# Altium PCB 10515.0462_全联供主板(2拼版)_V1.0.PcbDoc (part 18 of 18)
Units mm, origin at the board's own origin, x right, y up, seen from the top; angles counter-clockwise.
Board outline 282 x 198 mm, 2 copper layers (Top Layer, Bottom Layer); 716 components, 0 nets, 2364 pads, 1800 vias.
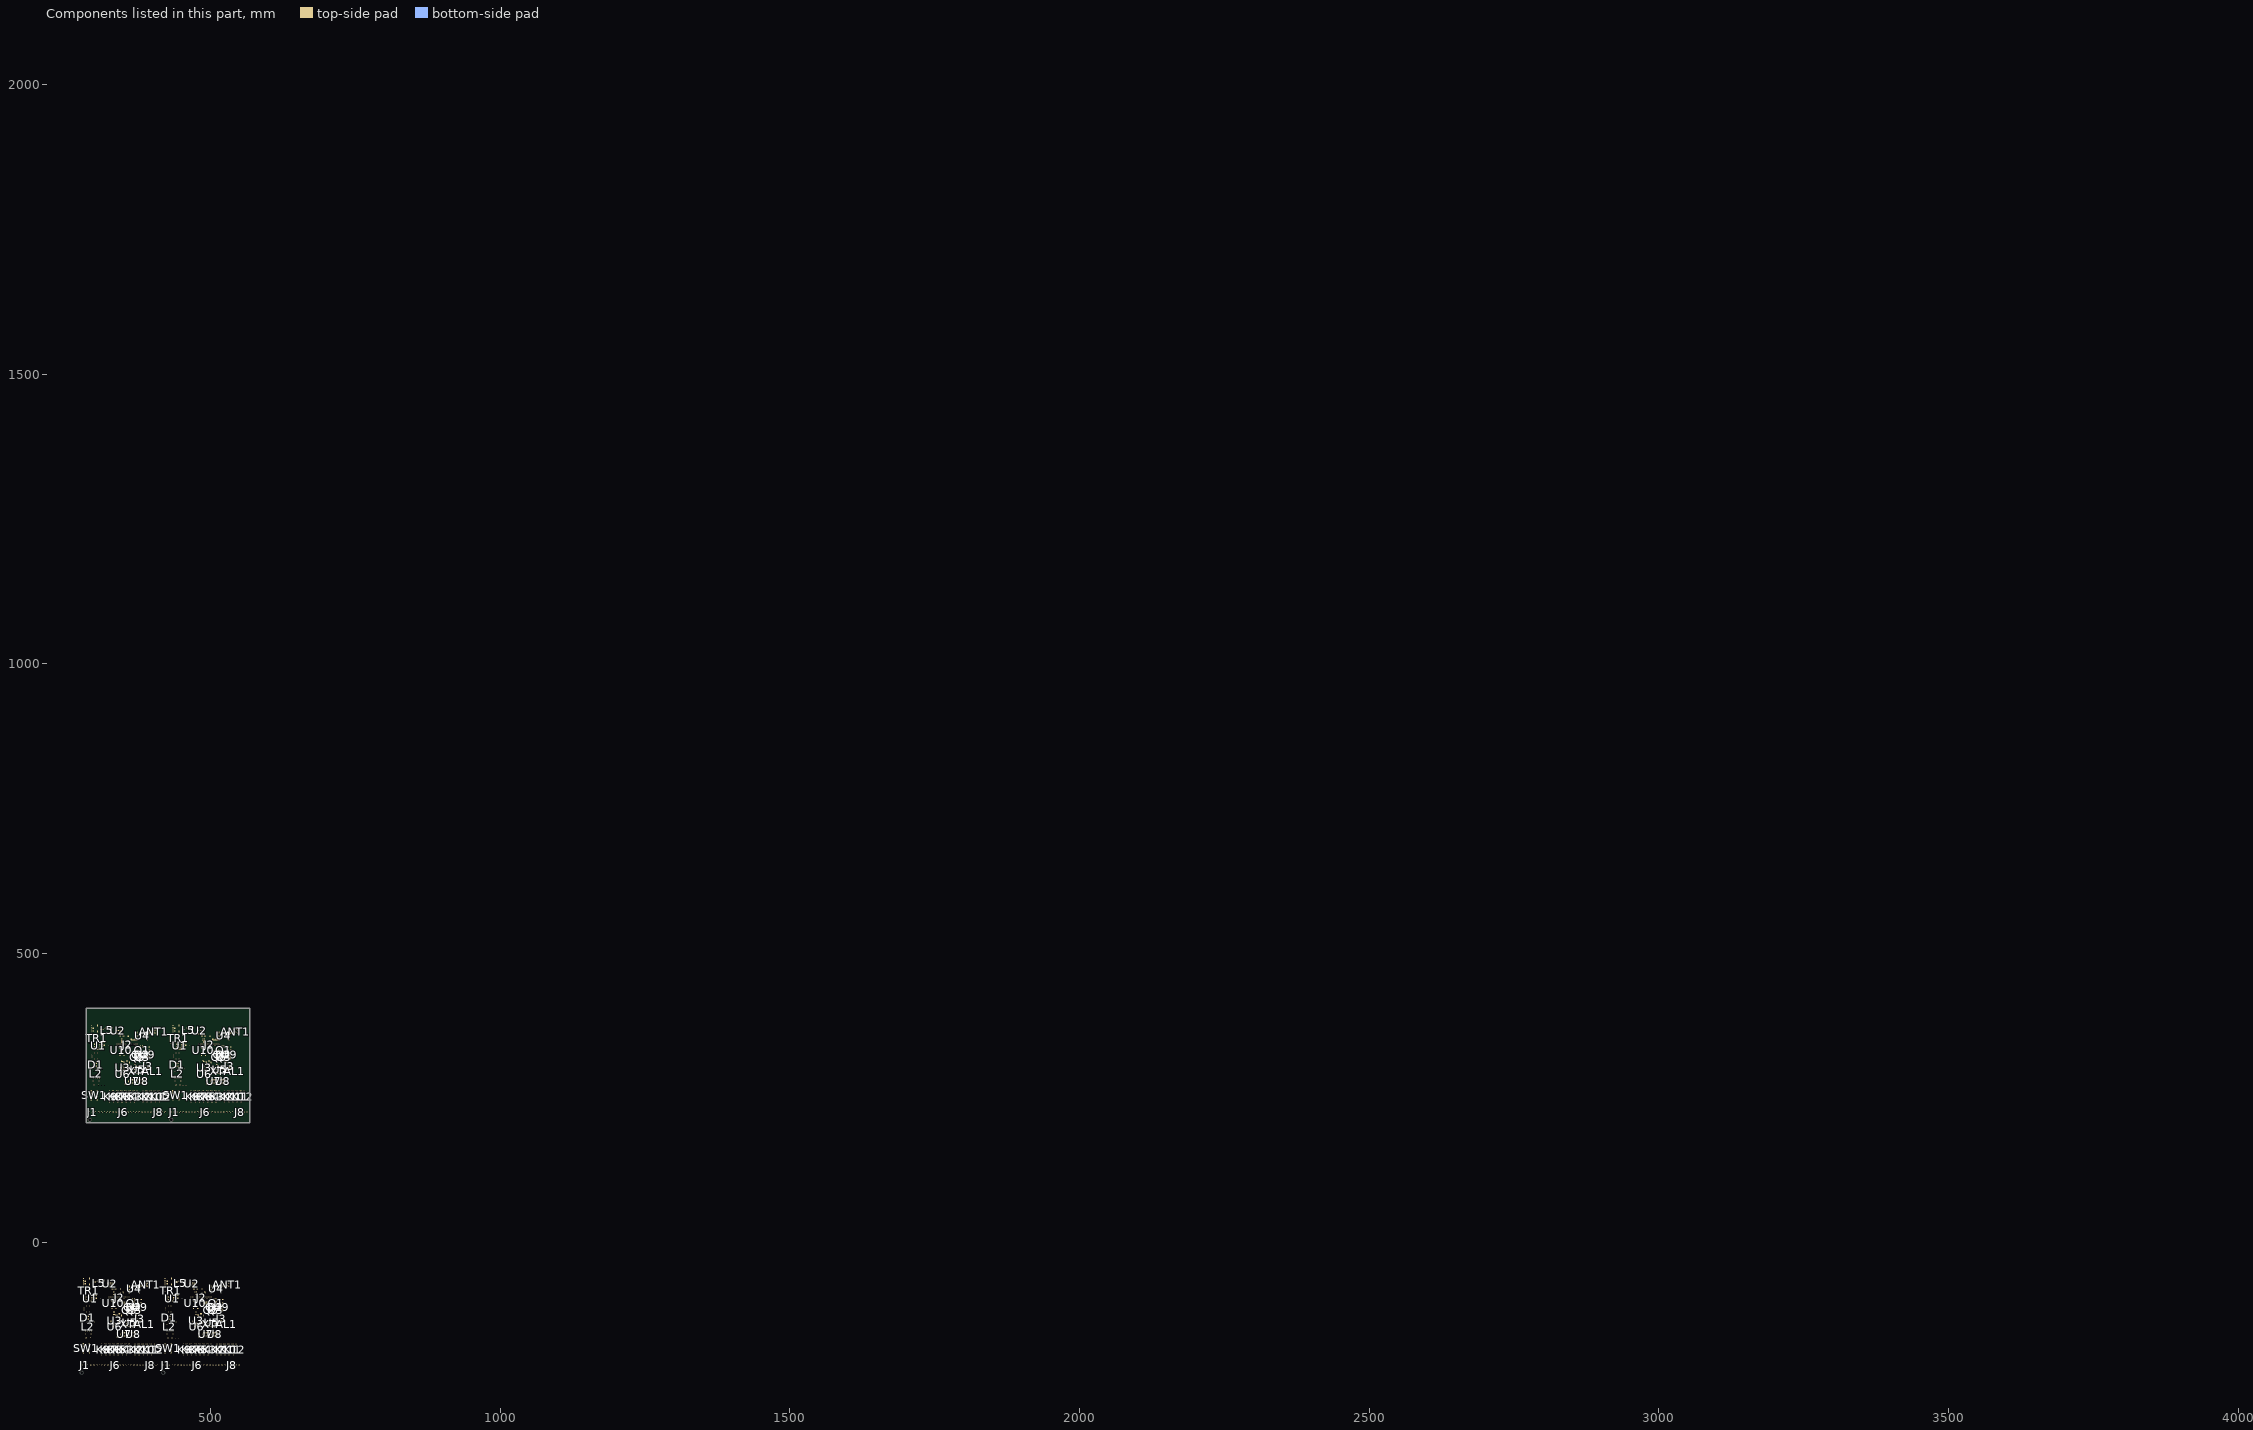
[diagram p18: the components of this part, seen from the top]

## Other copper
Top Layer:
  rectangle: 529.62,361.385 537.26,362.114
  rectangle: 536.974,362.114 537.768,362.977
  rectangle: 529.978,365.449 538.276,365.789
  rectangle: 530.148,362.02 530.402,365.576
  rectangle: 530.105,363.29 533.577,363.925
  rectangle: 532.688,361.707 533.577,363.544
  rectangle: 531.291,362.655 532.18,363.671
  rectangle: 476.698,364.306 477.57,365.476
  rectangle: 491.286,355.162 492.048,359.125
  rectangle: 388.62,361.385 396.26,362.114
  rectangle: 395.974,362.114 396.768,362.977
  rectangle: 388.978,365.449 397.276,365.789
  rectangle: 389.148,362.02 389.402,365.576
  rectangle: 389.105,363.29 392.577,363.925
  rectangle: 391.688,361.707 392.577,363.544
  rectangle: 390.291,362.655 391.18,363.671
  rectangle: 335.698,364.306 336.57,365.476
  rectangle: 350.286,355.162 351.048,359.125
  rectangle: 515.991,-75.21 523.631,-74.482
  rectangle: 523.345,-74.482 524.139,-73.618
  rectangle: 516.349,-71.146 524.647,-70.806
  rectangle: 516.519,-74.575 516.773,-71.019
  rectangle: 516.476,-73.305 519.948,-72.67
  rectangle: 519.059,-74.888 519.948,-73.051
  rectangle: 517.662,-73.94 518.551,-72.924
  rectangle: 463.07,-72.289 463.941,-71.119
  rectangle: 477.657,-81.433 478.419,-77.47
  rectangle: 374.991,-75.21 382.631,-74.482
  rectangle: 382.345,-74.482 383.139,-73.618
  rectangle: 375.349,-71.146 383.647,-70.806
  rectangle: 375.519,-74.575 375.773,-71.019
  rectangle: 375.476,-73.305 378.948,-72.67
  rectangle: 378.059,-74.888 378.948,-73.051
  rectangle: 376.662,-73.94 377.551,-72.924
  rectangle: 322.07,-72.289 322.941,-71.119
  rectangle: 336.657,-81.433 337.419,-77.47
  pour cut-out: 487.73,313.125 487.73,311.728 488.492,310.966 490.143,310.966 490.27,311.093 490.143,311.093 487.984,313.252 487.857,313.125
  pour cut-out: 522.909,319.729 523.925,319.729 524.941,320.745 524.941,320.872 524.306,321.507 523.29,321.507 522.909,321.126
  pour cut-out: 500.557,345.637 516.305,345.637 516.559,345.383 516.559,343.859 516.432,343.732 500.811,343.732 500.557,343.986
  pour cut-out: 519.861,322.65 521.004,322.65 521.512,322.142 521.512,320.745 521.131,320.364 519.988,320.364 519.734,320.618 519.734,322.523
  pour cut-out: 524.56,324.428 525.83,324.428 526.338,323.92 526.338,323.158 526.084,322.904 524.941,322.904 524.56,323.285
  pour cut-out: 514.781,334.715 518.337,334.715 518.591,334.461 518.591,328.492 517.448,327.349 514.527,327.349 514.4,327.476 514.4,334.334
  pour cut-out: 532.434,300.552 532.434,292.17 532.815,292.17 532.942,292.297 533.069,292.297 533.176,296.361 533.196,300.425 532.942,300.425 532.815,300.552
  pour cut-out: 488.111,348.177 488.111,345.47 488.619,344.962 488.619,336.493 488.492,336.366 488.111,336.366 487.476,337.001 487.476,347.542
  pour cut-out: 510.541,352.344 510.662,352.465 513.257,352.465 513.257,354.4 513.13,354.527 511.606,354.527 510.541,353.463
  pour cut-out: 498.144,355.67 497.509,355.035 497.509,351.098 498.017,351.098 498.144,351.225
  pour cut-out: 483.412,324.809 483.666,324.555 489,329.889 489,330.27 488.619,330.651 488.619,340.728 484.131,336.239 483.412,336.239
  pour cut-out: 516.94,324.047 521.893,324.047 522.528,324.682 522.528,333.572 521.385,334.715 516.686,334.715 516.432,334.461 516.432,324.555
  pour cut-out: 511.783,322.109 514.053,322.109 514.781,321.38 514.781,320.872 513.003,319.094 511.733,319.094 511.352,319.475 511.83,319.954 511.83,322.156
  pour cut-out: 529.005,321.126 530.148,321.126 530.148,323.666 529.64,324.174 528.243,324.174 528.243,321.888
  pour cut-out: 508.304,336.366 510.59,336.366 510.971,335.985 510.971,334.842 509.919,334.842 509.73,334.654 509.161,335.223 508.079,335.223 508.079,336.142
  pour cut-out: 474.522,370.656 474.522,368.37 473.887,368.37 473.887,370.021
  pour cut-out: 346.73,313.125 346.73,311.728 347.492,310.966 349.143,310.966 349.27,311.093 349.143,311.093 346.984,313.252 346.857,313.125
  pour cut-out: 381.909,319.729 382.925,319.729 383.941,320.745 383.941,320.872 383.306,321.507 382.29,321.507 381.909,321.126
  pour cut-out: 359.557,345.637 375.305,345.637 375.559,345.383 375.559,343.859 375.432,343.732 359.811,343.732 359.557,343.986
  pour cut-out: 378.861,322.65 380.004,322.65 380.512,322.142 380.512,320.745 380.131,320.364 378.988,320.364 378.734,320.618 378.734,322.523
  pour cut-out: 383.56,324.428 384.83,324.428 385.338,323.92 385.338,323.158 385.084,322.904 383.941,322.904 383.56,323.285
  pour cut-out: 373.781,334.715 377.337,334.715 377.591,334.461 377.591,328.492 376.448,327.349 373.527,327.349 373.4,327.476 373.4,334.334
  pour cut-out: 391.434,300.552 391.434,292.17 391.815,292.17 391.942,292.297 392.069,292.297 392.176,296.361 392.196,300.425 391.942,300.425 391.815,300.552
  pour cut-out: 347.111,348.177 347.111,345.47 347.619,344.962 347.619,336.493 347.492,336.366 347.111,336.366 346.476,337.001 346.476,347.542
  pour cut-out: 369.541,352.344 369.662,352.465 372.257,352.465 372.257,354.4 372.13,354.527 370.606,354.527 369.541,353.463
  pour cut-out: 357.144,355.67 356.509,355.035 356.509,351.098 357.017,351.098 357.144,351.225
  pour cut-out: 342.412,324.809 342.666,324.555 348,329.889 348,330.27 347.619,330.651 347.619,340.728 343.131,336.239 342.412,336.239
  pour cut-out: 375.94,324.047 380.893,324.047 381.528,324.682 381.528,333.572 380.385,334.715 375.686,334.715 375.432,334.461 375.432,324.555
  pour cut-out: 370.783,322.109 373.053,322.109 373.781,321.38 373.781,320.872 372.003,319.094 370.733,319.094 370.352,319.475 370.83,319.954 370.83,322.156
  pour cut-out: 388.005,321.126 389.148,321.126 389.148,323.666 388.64,324.174 387.243,324.174 387.243,321.888
  pour cut-out: 367.304,336.366 369.59,336.366 369.971,335.985 369.971,334.842 368.919,334.842 368.73,334.654 368.161,335.223 367.079,335.223 367.079,336.142
  pour cut-out: 333.522,370.656 333.522,368.37 332.887,368.37 332.887,370.021
  pour cut-out: 474.101,-123.47 474.101,-124.867 474.863,-125.629 476.514,-125.629 476.641,-125.502 476.514,-125.502 474.355,-123.343 474.228,-123.47
  pour cut-out: 509.28,-116.866 510.296,-116.866 511.312,-115.85 511.312,-115.723 510.677,-115.088 509.661,-115.088 509.28,-115.469
  pour cut-out: 486.928,-90.958 502.676,-90.958 502.93,-91.212 502.93,-92.736 502.803,-92.863 487.182,-92.863 486.928,-92.609
  pour cut-out: 506.232,-113.945 507.375,-113.945 507.883,-114.453 507.883,-115.85 507.502,-116.231 506.359,-116.231 506.105,-115.977 506.105,-114.072
  pour cut-out: 510.931,-112.167 512.201,-112.167 512.709,-112.675 512.709,-113.437 512.455,-113.691 511.312,-113.691 510.931,-113.31
  pour cut-out: 501.152,-101.88 504.708,-101.88 504.962,-102.134 504.962,-108.103 503.819,-109.246 500.898,-109.246 500.771,-109.119 500.771,-102.261
  pour cut-out: 518.805,-136.043 518.805,-144.425 519.186,-144.425 519.313,-144.298 519.44,-144.298 519.547,-140.234 519.567,-136.17 519.313,-136.17 519.186,-136.043
  pour cut-out: 474.482,-88.418 474.482,-91.125 474.99,-91.633 474.99,-100.102 474.863,-100.229 474.482,-100.229 473.847,-99.594 473.847,-89.053
  pour cut-out: 496.912,-84.251 497.034,-84.13 499.628,-84.13 499.628,-82.195 499.501,-82.068 497.977,-82.068 496.912,-83.133
  pour cut-out: 484.515,-80.925 483.88,-81.56 483.88,-85.497 484.388,-85.497 484.515,-85.37
  pour cut-out: 469.783,-111.786 470.037,-112.04 475.371,-106.706 475.371,-106.325 474.99,-105.944 474.99,-95.868 470.502,-100.356 469.783,-100.356
  pour cut-out: 503.311,-112.548 508.264,-112.548 508.899,-111.913 508.899,-103.023 507.756,-101.88 503.057,-101.88 502.803,-102.134 502.803,-112.04
  pour cut-out: 498.154,-114.487 500.424,-114.487 501.152,-115.215 501.152,-115.723 499.374,-117.501 498.104,-117.501 497.723,-117.12 498.202,-116.642 498.202,-114.439
  pour cut-out: 515.376,-115.469 516.519,-115.469 516.519,-112.929 516.011,-112.421 514.614,-112.421 514.614,-114.707
  pour cut-out: 494.675,-100.229 496.961,-100.229 497.342,-100.61 497.342,-101.753 496.29,-101.753 496.101,-101.941 495.532,-101.372 494.45,-101.372 494.45,-100.454
  pour cut-out: 460.893,-65.939 460.893,-68.225 460.258,-68.225 460.258,-66.574
  pour cut-out: 333.101,-123.47 333.101,-124.867 333.863,-125.629 335.514,-125.629 335.641,-125.502 335.514,-125.502 333.355,-123.343 333.228,-123.47
  pour cut-out: 368.28,-116.866 369.296,-116.866 370.312,-115.85 370.312,-115.723 369.677,-115.088 368.661,-115.088 368.28,-115.469
  pour cut-out: 345.928,-90.958 361.676,-90.958 361.93,-91.212 361.93,-92.736 361.803,-92.863 346.182,-92.863 345.928,-92.609
  pour cut-out: 365.232,-113.945 366.375,-113.945 366.883,-114.453 366.883,-115.85 366.502,-116.231 365.359,-116.231 365.105,-115.977 365.105,-114.072
  pour cut-out: 369.931,-112.167 371.201,-112.167 371.709,-112.675 371.709,-113.437 371.455,-113.691 370.312,-113.691 369.931,-113.31
  pour cut-out: 360.152,-101.88 363.708,-101.88 363.962,-102.134 363.962,-108.103 362.819,-109.246 359.898,-109.246 359.771,-109.119 359.771,-102.261
  pour cut-out: 377.805,-136.043 377.805,-144.425 378.186,-144.425 378.313,-144.298 378.44,-144.298 378.547,-140.234 378.567,-136.17 378.313,-136.17 378.186,-136.043
  pour cut-out: 333.482,-88.418 333.482,-91.125 333.99,-91.633 333.99,-100.102 333.863,-100.229 333.482,-100.229 332.847,-99.594 332.847,-89.053
  pour cut-out: 355.912,-84.251 356.034,-84.13 358.628,-84.13 358.628,-82.195 358.501,-82.068 356.977,-82.068 355.912,-83.133
  pour cut-out: 343.515,-80.925 342.88,-81.56 342.88,-85.497 343.388,-85.497 343.515,-85.37
  pour cut-out: 328.783,-111.786 329.037,-112.04 334.371,-106.706 334.371,-106.325 333.99,-105.944 333.99,-95.868 329.502,-100.356 328.783,-100.356
  pour cut-out: 362.311,-112.548 367.264,-112.548 367.899,-111.913 367.899,-103.023 366.756,-101.88 362.057,-101.88 361.803,-102.134 361.803,-112.04
  pour cut-out: 357.154,-114.487 359.424,-114.487 360.152,-115.215 360.152,-115.723 358.374,-117.501 357.104,-117.501 356.723,-117.12 357.202,-116.642 357.202,-114.439
  pour cut-out: 374.376,-115.469 375.519,-115.469 375.519,-112.929 375.011,-112.421 373.614,-112.421 373.614,-114.707
  pour cut-out: 353.675,-100.229 355.961,-100.229 356.342,-100.61 356.342,-101.753 355.29,-101.753 355.101,-101.941 354.532,-101.372 353.45,-101.372 353.45,-100.454
  pour cut-out: 319.893,-65.939 319.893,-68.225 319.258,-68.225 319.258,-66.574
Bottom Layer:
  rectangle: 488.746,344.901 490.778,346.145
  rectangle: 347.746,344.901 349.778,346.145
  rectangle: 475.117,-91.694 477.149,-90.45
  rectangle: 334.117,-91.694 336.149,-90.45
  pour cut-out: 482.904,340.303 484.555,338.652 516.051,338.652 516.305,338.906 516.305,343.478 514.882,344.901 508.313,344.901 507.704,345.51 507.542,345.51 506.399,344.367 483.412,344.367 482.904,343.859
  pour cut-out: 521.131,295.218 525.804,290.545 529.005,290.545 531.961,290.554 532.561,291.154 532.561,300.044 531.545,301.06 525.85,301.06 521.659,296.869 521.131,296.869 521.131,297.631 525.195,301.695 531.926,301.695 533.323,300.171 533.323,290.138 532.942,289.757 529.259,289.757 525.576,289.757 521.004,294.329 521.131,294.456
  pour cut-out: 474.522,370.656 474.522,368.37 473.887,368.37 473.887,370.148 474.014,370.148
  pour cut-out: 341.904,340.303 343.555,338.652 375.051,338.652 375.305,338.906 375.305,343.478 373.882,344.901 367.313,344.901 366.704,345.51 366.542,345.51 365.399,344.367 342.412,344.367 341.904,343.859
  pour cut-out: 380.131,295.218 384.804,290.545 388.005,290.545 390.961,290.554 391.561,291.154 391.561,300.044 390.545,301.06 384.85,301.06 380.659,296.869 380.131,296.869 380.131,297.631 384.195,301.695 390.926,301.695 392.323,300.171 392.323,290.138 391.942,289.757 388.259,289.757 384.576,289.757 380.004,294.329 380.131,294.456
  pour cut-out: 333.522,370.656 333.522,368.37 332.887,368.37 332.887,370.148 333.014,370.148
  pour cut-out: 469.275,-96.292 470.926,-97.943 502.422,-97.943 502.676,-97.689 502.676,-93.117 501.253,-91.694 494.684,-91.694 494.075,-91.085 493.913,-91.085 492.77,-92.228 469.783,-92.228 469.275,-92.736
  pour cut-out: 507.502,-141.377 512.175,-146.05 515.376,-146.05 518.332,-146.041 518.932,-145.441 518.932,-136.551 517.916,-135.535 512.221,-135.535 508.03,-139.726 507.502,-139.726 507.502,-138.964 511.566,-134.9 518.297,-134.9 519.694,-136.424 519.694,-146.457 519.313,-146.838 515.63,-146.838 511.947,-146.838 507.375,-142.266 507.502,-142.139
  pour cut-out: 460.893,-65.939 460.893,-68.225 460.258,-68.225 460.258,-66.447 460.385,-66.447
  pour cut-out: 328.275,-96.292 329.926,-97.943 361.422,-97.943 361.676,-97.689 361.676,-93.117 360.253,-91.694 353.684,-91.694 353.075,-91.085 352.913,-91.085 351.77,-92.228 328.783,-92.228 328.275,-92.736
  pour cut-out: 366.502,-141.377 371.175,-146.05 374.376,-146.05 377.332,-146.041 377.932,-145.441 377.932,-136.551 376.916,-135.535 371.221,-135.535 367.03,-139.726 366.502,-139.726 366.502,-138.964 370.566,-134.9 377.297,-134.9 378.694,-136.424 378.694,-146.457 378.313,-146.838 374.63,-146.838 370.947,-146.838 366.375,-142.266 366.502,-142.139
  pour cut-out: 319.893,-65.939 319.893,-68.225 319.258,-68.225 319.258,-66.447 319.385,-66.447

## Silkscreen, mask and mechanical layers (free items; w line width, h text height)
Top Overlay:
  drawing of 3110 lines, arcs and shapes, not listed
  text "10515.0462_全联供主板_V1.0" at 339.236,378.838 h3.5
  text "10515.0462_全联供主板_V1.0" at 480.236,378.838 h3.5
  text "20200526H1.6Sn" at 344.698,375.355 h3.5
  text "20200526H1.6Sn" at 485.698,375.355 h3.5
  text "PE" at 288.437,216.478 h3
  text "N1" at 305.582,216.478 h3
  text "L1" at 310.154,216.478 h3
  text "PE" at 429.437,216.478 h3
  text "N1" at 446.582,216.478 h3
  text "L1" at 451.154,216.478 h3
  text "L" at 300.121,216.351 h3
  text "L" at 441.121,216.351 h3
  text "N" at 294.787,216.224 h3
  text "N" at 435.787,216.224 h3
  text "水泵" at 306.471,213.303 h3
  text "水泵" at 447.471,213.303 h3
  text "外机联动开关" at 394.609,211.906 h2
  text "外机联动开关" at 535.609,211.906 h2
  text "制热开关" at 415.979,211.893 h2
  text "制热开关" at 556.979,211.893 h2
  text "执行器1" at 312.821,211.398 h3
  text "执行器2" at 323.017,211.398 h3
  text "执行器3" at 333.213,211.398 h3
  text "执行器4" at 343.41,211.398 h3
  text "执行器5" at 353.606,211.398 h3
  text "执行器6" at 363.802,211.398 h3
  text "执行器7" at 373.999,211.398 h3
  text "执行器8" at 384.195,211.398 h3
  text "执行器1" at 453.821,211.398 h3
  text "执行器2" at 464.017,211.398 h3
  text "执行器3" at 474.213,211.398 h3
  text "执行器4" at 484.41,211.398 h3
  text "执行器5" at 494.606,211.398 h3
  text "执行器6" at 504.802,211.398 h3
  text "执行器7" at 514.999,211.398 h3
  text "执行器8" at 525.195,211.398 h3
  text "制冷开关" at 405.785,208.731 h2
  text "制冷开关" at 546.785,208.731 h2
  text "10515.0462_全联供主板_V1.0" at 325.607,-57.757 h3.5
  text "10515.0462_全联供主板_V1.0" at 466.607,-57.757 h3.5
  text "20200407H1.6Sn" at 331.069,-61.24 h3.5
  text "20200407H1.6Sn" at 472.069,-61.24 h3.5
  text "PE" at 274.808,-220.117 h3
  text "N1" at 291.953,-220.117 h3
  text "L1" at 296.525,-220.117 h3
  text "PE" at 415.808,-220.117 h3
  text "N1" at 432.953,-220.117 h3
  text "L1" at 437.525,-220.117 h3
  text "L" at 286.492,-220.244 h3
  text "L" at 427.492,-220.244 h3
  text "N" at 281.158,-220.371 h3
  text "N" at 422.158,-220.371 h3
  text "水泵" at 292.842,-223.292 h3
  text "水泵" at 433.842,-223.292 h3
  text "外机联动开关" at 380.98,-224.689 h2
  text "外机联动开关" at 521.98,-224.689 h2
  text "制热开关" at 402.35,-224.703 h2
  text "制热开关" at 543.35,-224.703 h2
  text "执行器1" at 299.192,-225.197 h3
  text "执行器2" at 309.388,-225.197 h3
  text "执行器3" at 319.585,-225.197 h3
  text "执行器4" at 329.781,-225.197 h3
  text "执行器5" at 339.977,-225.197 h3
  text "执行器6" at 350.174,-225.197 h3
  text "执行器7" at 360.37,-225.197 h3
  text "执行器8" at 370.566,-225.197 h3
  text "执行器1" at 440.192,-225.197 h3
  text "执行器2" at 450.388,-225.197 h3
  text "执行器3" at 460.585,-225.197 h3
  text "执行器4" at 470.781,-225.197 h3
  text "执行器5" at 480.977,-225.197 h3
  text "执行器6" at 491.174,-225.197 h3
  text "执行器7" at 501.37,-225.197 h3
  text "执行器8" at 511.566,-225.197 h3
  text "制冷开关" at 392.156,-227.864 h2
  text "制冷开关" at 533.156,-227.864 h2
Bottom Overlay:
  circle w0.152: c1343.817,2045.24 r0.3
  circle w0.152: c1345.817,2045.24 r0.3
  circle w0.152: c1347.817,2045.24 r0.3
  circle w0.152: c1349.817,2045.24 r0.3
  circle w0.152: c1351.817,2045.24 r0.3
  circle w0.152: c1353.817,2045.24 r0.3
  circle w0.152: c1355.817,2045.24 r0.3
  circle w0.152: c1357.817,2045.24 r0.3
  circle w0.152: c1359.817,2045.24 r0.3
  circle w0.152: c1361.817,2045.24 r0.3
  circle w0.152: c1363.817,2045.24 r0.3
  circle w0.152: c1365.817,2045.24 r0.3
  rectangle: 441.756,308.553 442.772,311.347
  rectangle: 300.756,308.553 301.772,311.347
  rectangle: 428.127,-128.042 429.143,-125.248
  rectangle: 287.127,-128.042 288.143,-125.248
  lines w0.127: 271.379,-217.887 412.379,-217.887 553.379,-217.887 ; 271.379,-41.887 412.379,-41.887 553.379,-41.887 ; 285.008,218.708 426.008,218.708 567.008,218.708 ; 285.008,394.708 426.008,394.708 567.008,394.708
  lines w0.152: 1341.317,2044.24 1341.317,2043.64 1341.817,2043.64 1341.817,2047.14 1341.317,2047.14 1341.317,2046.54 ; 1341.817,2044.24 1340.817,2044.24 1340.817,2042.34 1368.817,2042.34 1368.817,2044.24 1367.817,2044.24 ; 1341.817,2046.54 1340.817,2046.54 1340.817,2047.74 1368.817,2047.74 1368.817,2046.54 1367.817,2046.54 ; 1368.317,2044.24 1368.317,2043.64 1367.817,2043.64 1367.817,2047.14 1368.317,2047.14 1368.317,2046.54 ; 1342.417,2042.84 1367.217,2042.84 1367.217,2046.34 1364.692,2046.34 1364.692,2047.24 1344.942,2047.24 1344.942,2046.34 1342.417,2046.34 1342.417,2042.84
Mechanical 8:
  drawing of 280 lines, arcs and shapes, not listed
